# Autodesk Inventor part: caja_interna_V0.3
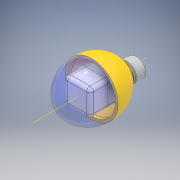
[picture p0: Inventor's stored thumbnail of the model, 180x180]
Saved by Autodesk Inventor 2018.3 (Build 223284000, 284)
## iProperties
Created: 2018-09
Part Number: caja_interna_V0.3
Material: Generic
Document SubType Name: Modeling
Designer: Gordillo
Density: 1 g/cm^3
Appearance: Default
Author: Gordillo
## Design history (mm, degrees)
sketch "Sketch1"
  geometry: L1 (75, 75)-(-75, 75); L2 (-75, 75)-(-75, -75); L3 (-75, -75)-(75, -75); L4 (75, -75)-(75, 75); L5 (-105, 0)-(105, 0) reference; L6 (0, -105)-(0, 105) reference; 1 further point
  constraints: 8 end point, 2 parallel, 1 horizontal, 1 perpendicular, 2 other
  dimensions: "d0" = 150 distance of L3.end L2.end; "d1" = 150 distance of L2.end L1.end
extrude "Extrusion1" new body sketch "Sketch1" distance "d2" = 150; taper "d3" = 0 deg
fillet "Fillet1" dims "d5" = 20
sketch "Sketch2"
  geometry: L1 (20, 75)-(150, 75) reference; L2 (85, 75)-(85, -75); L3 (150, -75)-(20, -75) reference; L4 (85, 75)-(85, 155); L5 (85, 0)-(-115, 0); L6 (-172.525, 0)-(285.421, 0) reference; A1 r 203.001 centre (82.249, -47.982) between (85, 155) and (-115, 0); 1 further point
  constraints: 6 end point, 3 midpoint, 2 point on circle, 1 centre point, 1 horizontal, 1 vertical
  dimensions: "d6" = 200 distance of L5.start L5.end; "d8" = 80 distance of L2.start L4.end
revolve "Revolution1" sketch "Sketch2" stored, may be unused: angle "d9" = 90 deg
combine "Combine1"
shell "Shell2" dims "d10" = 25
sketch "Sketch3"
  geometry: L1 (50, 50)-(50, -50) reference; L2 (50, -50)-(-50, -50) reference; L3 (-50, -50)-(-50, 50) reference; L4 (-50, 50)-(50, 50) reference; L5 (55, 75)-(-55, 75) reference; L6 (-75, 55)-(-75, -55) reference; L7 (-55, -75)-(55, -75) reference; L8 (75, -55)-(75, 55) reference; L9 (-55, 75)-(55, 75) reference; L10 (75, 55)-(75, -55) reference; L11 (55, -75)-(-55, -75) reference; L12 (-75, -55)-(-75, 55) reference; L13 (-55, 75)-(55, 75) reference; L14 (55, 75)-(-55, 75); L15 (-55, 75)-(-75, 55); L16 (-75, -55)-(-75, 55) reference; L17 (-75, -55)-(-55, -75); L18 (75, 55)-(75, -55) reference; L19 (55, -75)-(75, -55); L20 (75, -55)-(75, 55); L21 (-75, 55)-(-55, 55) reference; L22 (-75, 55)-(-75, -55); L23 (-55, -75)-(55, -75); C1 r 155 at (0, 0) reference; C2 r 139 at (0, 0); C3 r 155 at (0, 0) reference; A1 r 20 centre (55, 55) between (75, 55) and (55, 75) reference; A2 r 20 centre (-55, 55) between (-55, 75) and (-75, 55) reference; A3 r 20 centre (-55, -55) between (-75, -55) and (-55, -75) reference; A4 r 20 centre (55, -55) between (55, -75) and (75, -55) reference; A5 r 20 centre (-55, 55) between (-55, 75) and (-75, 55) reference; A6 r 20 centre (55, 55) between (75, 55) and (55, 75) reference; A7 r 20 centre (55, -55) between (55, -75) and (75, -55) reference; A8 r 20 centre (-55, -55) between (-75, -55) and (-55, -75) reference; A9 r 20 centre (55, 55) between (75, 55) and (55, 75) reference; A10 r 20 centre (55, 55) between (75, 55) and (55, 75); A11 r 20 centre (55, -55) between (55, -75) and (75, -55) reference; A12 r 20 centre (55, -55) between (55, -75) and (75, -55); A13 r 20 centre (-55, -55) between (-75, -55) and (-55, -75); A14 r 20 centre (-55, 55) between (-55, 75) and (-75, 55) reference; A15 r 20 centre (-55, 55) between (-55, 75) and (-75, 55); A16 r 20 centre (-55, -55) between (-75, -55) and (-55, -75); A17 r 20 centre (-55, -55) between (-75, -55) and (-55, -75); A18 r 20 centre (55, -55) between (55, -75) and (75, -55); A19 r 20 centre (-55, -55) between (-75, -55) and (-55, -75) reference; A20 r 20 centre (-55, -55) between (-75, -55) and (-55, -75); 1 further point
  constraints: 16 point on circle, 14 end point, 9 centre point, 3 perpendicular, 3 tangent, 2 collinear, 1 concentric, 1 vertical
  dimensions: "d11" = 16 radial gap between concentric circles of C1 C2
extrude "Extrusion2" join sketch "Sketch3" distance "d12" = 20; taper "d13" = 0 deg
sketch "Sketch4"
  geometry: L1 (139, 105)-(-139, 105) reference; L2 (155, 85)-(-155, 85) reference; L3 (139, 85)-(139, 105) reference; L4 (139, 105)-(-139, 105) reference; L5 (-139, 85)-(139, 85) reference; L6 (-75, 20)-(-75, 150) reference; L7 (-75, 150)-(-55, 150) reference; L8 (-155, 85)-(-139, 85); L9 (-139, 85)-(-139, 105); L10 (155, 85)-(-155, 85) reference; L11 (-139, 105)-(-75, 105); L12 (0, 85)-(0, 285); L13 (-75, 105)-(0, 105); L14 (0, -165.711)-(0, 434.264) reference; L15 (0, 269)-(-55, 269); L16 (-55, 269)-(-55, 264.514); L17 (0, 269)-(0, 263); L18 (0, 269)-(-55, 269); L19 (-55, 269)-(-55, 264.514); L20 (-87, 242.257)-(-67, 242.257); L21 (-67, 242.257)-(-67, 257.263); A1 r 195 centre (39.787, 94.102) between (0, 285) and (-155, 85); A2 r 177.861 centre (38.165, 89.282) between (0, 263) and (-139, 105); A3 r 195 centre (39.787, 94.102) between (-55, 264.514) and (-155, 85); A4 r 177.861 centre (38.165, 89.282) between (0, 263) and (-139, 105); 2 further points
  constraints: 24 end point, 11 point on circle, 5 point on line, 4 centre point, 4 perpendicular, 3 vertical, 2 collinear, 2 concentric, 2 midpoint, 1 horizontal
  dimensions: "d14" = 200 distance of L12.start L12.end; "d15" = 195 radius of A1; "d16" = 22 distance of L12.end L17.end; "d26" = 55 distance of L15.start L15.end; "d27" = 16 distance from line of L12.end L15; "d28" = 177.86112 radius of A2; "d30" = 12 distance between parallel lines of L16 L21; "d31" = 20 distance of L20.start L20.end
  node "Projected Loop3"
  node "Projected Loop4"
derived "tubo_electrovalvula_V0.1.ipt"
feature "Move Body1"
feature "Move Body3"
revolve "Revolution4" stored, may be unused: angle "d32" = 90 deg
workplane "Work Plane1"
sketch "Sketch5"
  geometry: L1 (67, 87.263)-(-67, 87.263) reference; L2 (0, 87.263)-(0, 72.257); L3 (67, 72.257)-(-67, 72.257) reference; 2 further points
  constraints: 3 midpoint, 2 end point
hole "Hole1" sketch "Sketch5" at (0, 79.76) diameter "d33" = 3; stored, may be unused: countersink angle "d37" = 90 deg, drill point angle "d39" = 118 deg; dims "d34" = 6, "d35" = 4, "d36" = 2, "d38" = 6
sketch "Sketch6"
  geometry: C1 r 1.5 at (0, 18.105); A1 r 1.5 centre (0, 18.105) between (0, 16.605) and (0, 19.605) reference; A2 r 1.5 centre (0, 18.105) between (0, 16.605) and (0, 19.605) reference; 1 further point
  constraints: 1 centre point, 1 coincident, 1 concentric
extrude "Extrusion3" cut sketch "Sketch6" distance "d40" = 20; taper "d41" = 0 deg
pattern_circular "Circular Pattern1" dims angle "d43" = 360 deg
node "cajacorchopan"
node "semicirculo_inferior"
node "Projected Loop1"
node "Projected Loop2"
feature "Solid1::tubo_electrovalvula_V0.1.ipt" dims "d18" = 10
tag "TaggingFeature1"
node "semicirculo_superior"
node "tubo inflado"
other parameters: "d19" = 270 deg, "d23" = 0
